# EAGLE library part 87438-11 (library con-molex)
Wire-to-Board 1.50mm (.059") Pitch Header - Right Angle, SMT, Shrouded Source: http://www.molex.com/product/micro/87438.html
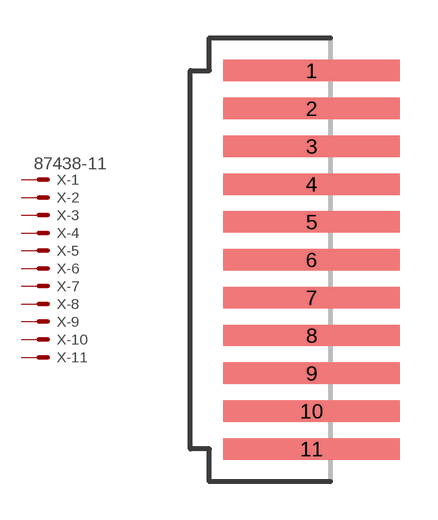
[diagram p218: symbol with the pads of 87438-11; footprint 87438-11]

Designator prefix X; gates -1=MV -2=M -3=M -4=M -5=M -6=M -7=M -8=M -9=M -10=M -11=M

## 87438-11 (MPN: 87438-1142; OC_FARNELL: unknown; OC_NEWARK: 94M1098)  [87438-11]
1  -1:S  pas
2  -2:S  pas
3  -3:S  pas
4  -4:S  pas
5  -5:S  pas
6  -6:S  pas
7  -7:S  pas
8  -8:S  pas
9  -9:S  pas
10  -10:S  pas
11  -11:S  pas

## Footprint 87438-11 (pad centres in mm)
Wire-to-Board 1.50mm (.059") Pitch Header - Right Angle, SMT, Shrouded Source: http://www.molex.com/product/micro/87438.html
smd 7 x 0.85: 1 0,7.5; 2 0,6; 3 0,4.5; 4 0,3; 5 0,1.5; 6 0,0; 7 0,-1.5; 8 0,-3; 9 0,-4.5; 10 0,-6; 11 0,-7.5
